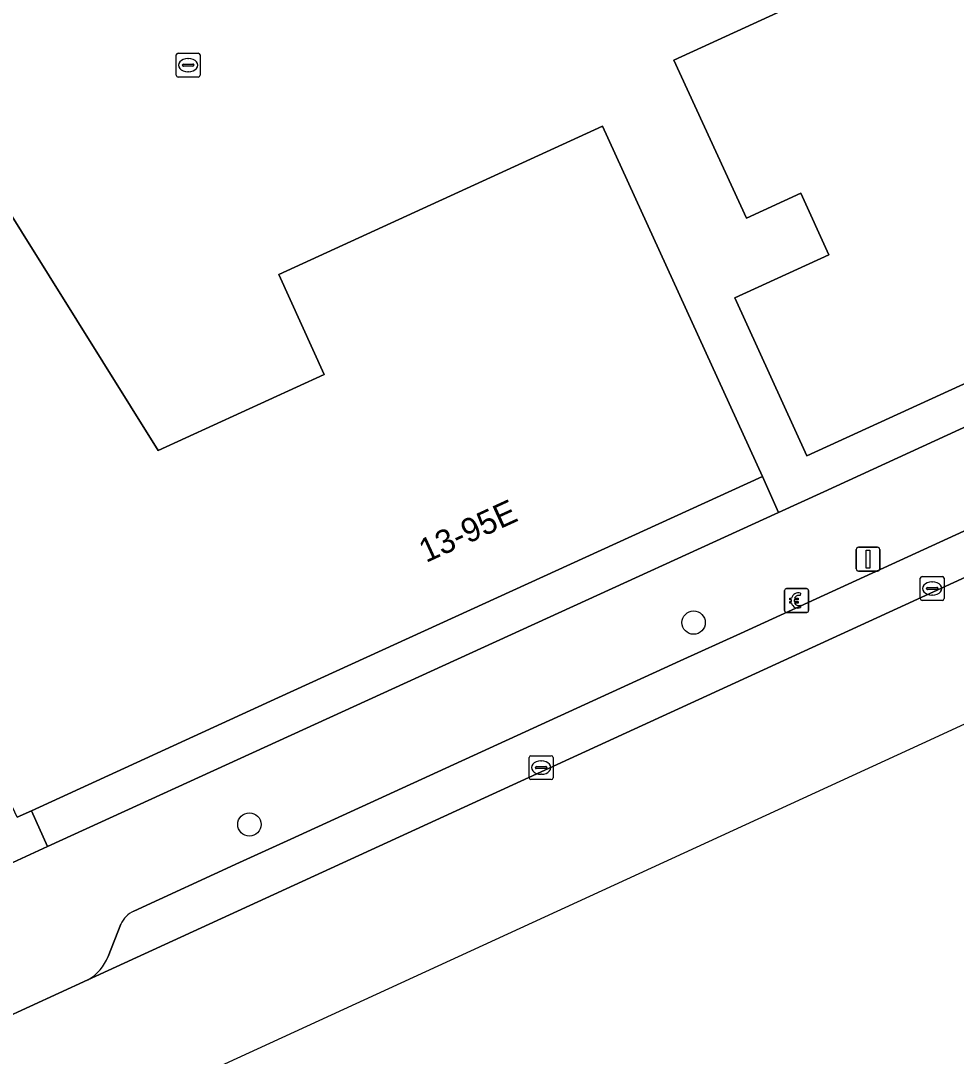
# Model space of a CAD drawing. Extents: x 160377 to 161131, y 383938 to 384853.
# Drawn here: x 161013.88 to 161053.13, y 383997.82 to 384041.25 of the extents above; entities that cross this region are included whole.
import ezdxf

# ---------------------------------------------------------------- set-up
doc = ezdxf.new("R2010")
doc.units = 0
for name, color, linetype in [('IMGEO_Betaalautomaat', 7, 'Continuous'), ('IMGEO_Boom', 7, 'Continuous'), ('IMGEO_Erf', 7, 'Continuous'), ('IMGEO_Kolk', 7, 'Continuous'), ('IMGEO_Lichtmast', 7, 'Continuous'), ('IMGEO_Pand', 7, 'Continuous'), ('IMGEO_Pand_nummerreeks', 7, 'Continuous'), ('IMGEO_Parkeervlak_open', 7, 'Continuous'), ('IMGEO_Rijbaan_lokaal_open', 7, 'Continuous'), ('IMGEO_Voetpad_open', 7, 'Continuous')]:
    doc.layers.add(name, color=color, linetype=linetype)

msp = doc.modelspace()

# ---------------------------------------------------------------- linework, layer by layer
at = {"layer": 'IMGEO_Betaalautomaat'}
for p, q in [((161045.925, 384016.507), (161045.925, 384017.348)), ((161045.925, 384017.348), (161045.925, 384016.507)), ((161046, 384017.431), (161046.841, 384017.431)), ((161046.841, 384017.431), (161046, 384017.431)), ((161046.924, 384017.357), (161046.924, 384016.516)), ((161046.924, 384016.516), (161046.924, 384017.357)), ((161046.208, 384016.895), (161046.208, 384016.963)), ((161046.329, 384016.963), (161046.329, 384016.895)), ((161046.587, 384017.236), (161046.57, 384017.136)), ((161046.85, 384016.432), (161046.009, 384016.432)), ((161046.009, 384016.432), (161046.85, 384016.432)), ((161046.574, 384016.73), (161046.596, 384016.643))]:
    msp.add_line(p, q, dxfattribs=at)
for points in [[(161046.208, 384016.963), (161046.139, 384016.963), (161046.139, 384017.032), (161046.218, 384017.032)], [(161046.213, 384016.826), (161046.139, 384016.826), (161046.139, 384016.895), (161046.208, 384016.895)], [(161046.34, 384017.032), (161046.487, 384017.032), (161046.487, 384016.963), (161046.329, 384016.963)], [(161046.329, 384016.895), (161046.487, 384016.895), (161046.487, 384016.826), (161046.343, 384016.826)]]:
    msp.add_lwpolyline(points, dxfattribs=at)
for centre, radius, start, end in [((161046.003, 384017.354), 0.0779, 92.4484, 184.2845), ((161046.003, 384017.354), 0.0779, 92.4484, 184.2845), ((161046.847, 384017.354), 0.0779, 2.4484, 94.2845), ((161046.847, 384017.354), 0.0779, 2.4484, 94.2845), ((161046.501, 384016.956), 0.293, 73.014, 165.0139), ((161046.507, 384016.969), 0.179, 69.3236, 159.5683), ((161046.003, 384016.51), 0.0779, 182.4484, 274.2845), ((161046.003, 384016.51), 0.0779, 182.4484, 274.2845), ((161046.474, 384016.881), 0.267, 191.8096, 297.0389), ((161046.507, 384016.896), 0.179, 202.7625, 291.8693), ((161046.847, 384016.51), 0.0779, 272.4484, 4.2845), ((161046.847, 384016.51), 0.0779, 272.4484, 4.2845)]:
    msp.add_arc(centre, radius, start, end, dxfattribs=at)
at = {"layer": 'IMGEO_Boom'}
for centre in [(161042.106, 384016.005), (161023.471, 384007.54)]:
    msp.add_circle(centre, 0.489, dxfattribs=at)
at = {"layer": 'IMGEO_Erf'}
for points in [[(161069.225, 384033.241), (161046.86, 384023.007), (161043.831, 384029.622), (161047.785, 384031.433), (161046.605, 384034.011), (161044.32, 384032.962), (161041.279, 384039.589), (161048.269, 384042.808)], [(161009.325, 384039.731), (161019.643, 384023.219), (161026.605, 384026.414), (161024.703, 384030.612), (161038.283, 384036.825), (161044.998, 384022.139), (161045.662, 384020.629), (161047.562, 384021.484), (161073.95, 384033.616), (161074.612, 384033.993)]]:
    msp.add_lwpolyline(points, dxfattribs=at)
at = {"layer": 'IMGEO_Kolk'}
for p, q in [((161020.476, 384039.887), (161021.328, 384039.887)), ((161020.401, 384038.961), (161020.401, 384039.813)), ((161020.703, 384039.43), (161021.101, 384039.43)), ((161020.889, 384039.667), (161020.914, 384039.667)), ((161021.402, 384039.813), (161021.402, 384038.961)), ((161020.66, 384039.381), (161020.66, 384039.393)), ((161021.098, 384039.344), (161020.7, 384039.344)), ((161020.912, 384039.107), (161020.887, 384039.107)), ((161021.144, 384039.393), (161021.144, 384039.381)), ((161021.328, 384038.887), (161020.476, 384038.887)), ((161051.614, 384017.011), (161051.614, 384017.863)), ((161051.689, 384017.937), (161052.541, 384017.937)), ((161052.102, 384017.717), (161052.127, 384017.717)), ((161052.615, 384017.863), (161052.615, 384017.011)), ((161051.873, 384017.431), (161051.873, 384017.443)), ((161052.311, 384017.394), (161051.913, 384017.394)), ((161051.916, 384017.48), (161052.314, 384017.48)), ((161052.357, 384017.443), (161052.357, 384017.431)), ((161052.541, 384016.937), (161051.689, 384016.937)), ((161052.125, 384017.157), (161052.1, 384017.157)), ((161035.208, 384009.497), (161035.208, 384010.349)), ((161035.283, 384010.423), (161036.135, 384010.423)), ((161036.209, 384010.349), (161036.209, 384009.497)), ((161035.467, 384009.917), (161035.467, 384009.929)), ((161035.51, 384009.966), (161035.908, 384009.966)), ((161035.696, 384010.203), (161035.721, 384010.203)), ((161035.951, 384009.929), (161035.951, 384009.917)), ((161035.905, 384009.88), (161035.507, 384009.88)), ((161035.719, 384009.643), (161035.694, 384009.643)), ((161036.135, 384009.423), (161035.283, 384009.423))]:
    msp.add_line(p, q, dxfattribs=at)
for points in [[(161020.476, 384039.887), (161021.328, 384039.887)], [(161020.401, 384038.961), (161020.401, 384039.813)], [(161021.402, 384039.813), (161021.402, 384038.961)], [(161021.328, 384038.887), (161020.476, 384038.887)], [(161051.614, 384017.011), (161051.614, 384017.863)], [(161051.689, 384017.937), (161052.541, 384017.937)], [(161052.615, 384017.863), (161052.615, 384017.011)], [(161052.541, 384016.937), (161051.689, 384016.937)], [(161035.208, 384009.497), (161035.208, 384010.349)], [(161035.283, 384010.423), (161036.135, 384010.423)], [(161036.209, 384010.349), (161036.209, 384009.497)], [(161036.135, 384009.423), (161035.283, 384009.423)]]:
    msp.add_lwpolyline(points, dxfattribs=at)
for centre, radius, start, end in [((161020.478, 384039.811), 0.0765, 91.552, 178.448), ((161020.478, 384039.811), 0.0765, 91.552, 178.448), ((161021.326, 384039.811), 0.0765, 1.552, 88.448), ((161021.326, 384039.811), 0.0765, 1.552, 88.448), ((161020.7, 384039.39), 0.0403, 85.8775, 175.7526), ((161021.105, 384039.392), 0.0386, 1.7309, 96.639), ((161020.697, 384039.38), 0.0366, 178.938, 274.7102), ((161021.101, 384039.387), 0.043, 264.8664, 352.4533), ((161020.478, 384038.963), 0.0765, 181.552, 268.448), ((161020.478, 384038.963), 0.0765, 181.552, 268.448), ((161021.326, 384038.963), 0.0765, 271.552, 358.448), ((161021.326, 384038.963), 0.0765, 271.552, 358.448), ((161051.691, 384017.861), 0.0765, 91.552, 178.448), ((161051.691, 384017.861), 0.0765, 91.552, 178.448), ((161052.539, 384017.861), 0.0765, 1.552, 88.448), ((161052.539, 384017.861), 0.0765, 1.552, 88.448), ((161051.913, 384017.44), 0.0403, 85.8775, 175.7526), ((161051.91, 384017.43), 0.0366, 178.938, 274.7102), ((161052.314, 384017.437), 0.043, 264.8664, 352.4533), ((161052.318, 384017.442), 0.0386, 1.7309, 96.639), ((161051.691, 384017.013), 0.0765, 181.552, 268.448), ((161051.691, 384017.013), 0.0765, 181.552, 268.448), ((161052.539, 384017.013), 0.0765, 271.552, 358.448), ((161052.539, 384017.013), 0.0765, 271.552, 358.448), ((161035.285, 384010.347), 0.0765, 91.552, 178.448), ((161035.285, 384010.347), 0.0765, 91.552, 178.448), ((161036.133, 384010.347), 0.0765, 1.552, 88.448), ((161036.133, 384010.347), 0.0765, 1.552, 88.448), ((161035.507, 384009.926), 0.0403, 85.8775, 175.7526), ((161035.504, 384009.916), 0.0366, 178.938, 274.7102), ((161035.908, 384009.923), 0.043, 264.8664, 352.4533), ((161035.912, 384009.928), 0.0386, 1.7309, 96.639), ((161035.285, 384009.499), 0.0765, 181.552, 268.448), ((161035.285, 384009.499), 0.0765, 181.552, 268.448), ((161036.133, 384009.499), 0.0765, 271.552, 358.448), ((161036.133, 384009.499), 0.0765, 271.552, 358.448)]:
    msp.add_arc(centre, radius, start, end, dxfattribs=at)
for centre, major_axis, ratio, start_param, end_param in [((161020.888, 384039.387), (-0.387, 0.002), 0.722429, 4.712389, 7.853982), ((161020.913, 384039.387), (-0.39, 0.002), 0.717154, 1.570796, 4.712389), ((161052.101, 384017.437), (-0.387, 0.002), 0.722429, 4.712389, 7.853982), ((161052.126, 384017.437), (-0.39, 0.002), 0.717154, 1.570796, 4.712389), ((161035.695, 384009.923), (-0.387, 0.002), 0.722429, 4.712389, 7.853982), ((161035.72, 384009.923), (-0.39, 0.002), 0.717154, 1.570796, 4.712389)]:
    msp.add_ellipse(centre, major_axis=major_axis, ratio=ratio, start_param=start_param, end_param=end_param, dxfattribs=at)
at = {"layer": 'IMGEO_Lichtmast'}
for p, q in [((161048.926, 384018.266), (161048.926, 384019.066)), ((161048.926, 384019.066), (161048.926, 384018.266)), ((161049.026, 384019.166), (161049.816, 384019.166)), ((161049.816, 384019.166), (161049.026, 384019.166)), ((161049.916, 384019.066), (161049.916, 384018.266)), ((161049.916, 384018.266), (161049.916, 384019.066)), ((161049.816, 384018.166), (161049.026, 384018.166)), ((161049.026, 384018.166), (161049.816, 384018.166))]:
    msp.add_line(p, q, dxfattribs=at)
msp.add_lwpolyline([(161049.346, 384019.041), (161049.496, 384019.041), (161049.496, 384018.291), (161049.346, 384018.291), (161049.346, 384019.041)], dxfattribs=at)
for centre, start, end in [((161049.026, 384019.066), 90, 180), ((161049.026, 384019.066), 90, 180), ((161049.816, 384019.066), 0, 90), ((161049.816, 384019.066), 360, 90), ((161049.026, 384018.266), 180, 270), ((161049.026, 384018.266), 180, 270), ((161049.816, 384018.266), 270, 0), ((161049.816, 384018.266), 270, 0)]:
    msp.add_arc(centre, 0.1, start, end, dxfattribs=at)
at = {"layer": 'IMGEO_Pand'}
for points in [[(161048.269, 384042.808), (161041.279, 384039.589), (161044.32, 384032.962), (161046.605, 384034.011), (161047.785, 384031.433), (161043.831, 384029.622), (161046.86, 384023.007), (161069.225, 384033.241)], [(161013.73, 384007.845), (161014.324, 384008.117), (161024.693, 384012.86), (161044.998, 384022.139), (161038.283, 384036.825), (161024.703, 384030.612), (161026.605, 384026.414), (161019.643, 384023.219), (161009.325, 384039.731)]]:
    msp.add_lwpolyline(points, dxfattribs=at)
at = {"layer": 'IMGEO_Parkeervlak_open'}
for points in [[(161074.162, 384029.337), (161044.069, 384015.547), (161041.548, 384014.402), (161025.206, 384006.923), (161023.057, 384005.944), (161018.622, 384003.898)], [(161016.691, 384001.021), (161077.47, 384028.899)], [(161018.081, 384003.352), (161017.544, 384002.003)]]:
    msp.add_lwpolyline(points, dxfattribs=at)
for centre, radius, start, end in [((161018.995, 384002.987), 0.984, 112.279, 158.2481), ((161015.766, 384002.686), 1.905, 299.0539, 338.9886)]:
    msp.add_arc(centre, radius, start, end, dxfattribs=at)
at = {"layer": 'IMGEO_Rijbaan_lokaal_open'}
msp.add_lwpolyline([(160907.425, 383944.713), (161008.487, 383991.097), (161051.698, 384010.93), (161091.48, 384029.287), (161091.391, 384029.491), (161089.312, 384034.241), (161088.837, 384034.033), (161088.05, 384033.688), (161078.568, 384029.392), (161077.47, 384028.899), (161016.691, 384001.021), (161013.046, 383999.338), (161012.775, 383999.215), (160997.494, 383992.318), (160995.778, 383991.468), (160976.307, 383982.559), (160969.412, 383979.39), (160962.893, 383976.427), (160952.387, 383971.601), (160950.34, 383970.771), (160939.561, 383966.391), (160931.592, 383964.679)], dxfattribs=at)
at = {"layer": 'IMGEO_Voetpad_open'}
for points in [[(161002.829, 384017.939), (161003.747, 384018.488), (161000, 384024.459), (160997.809, 384027.95), (160996.896, 384027.38), (160994.826, 384030.694), (160995.573, 384031.201), (160988.066, 384043.19), (160987.32, 384042.691), (160979.403, 384055.414), (160978.717, 384056.538), (160978.313, 384057.179), (160976.857, 384059.536), (160975.962, 384059.006), (161009.9, 384004.269), (161015.004, 384006.614), (161014.324, 384008.117), (161013.73, 384007.845), (161013.438, 384008.48), (161009.85, 384006.769)], [(161024.693, 384012.86), (161014.324, 384008.117), (161015.004, 384006.614), (161045.662, 384020.629), (161044.998, 384022.139)]]:
    msp.add_lwpolyline(points, close=True, dxfattribs=at)
for points in [[(161077.47, 384028.899), (161078.568, 384029.392), (161078.101, 384030.377), (161088.373, 384035.017), (161088.837, 384034.033), (161089.312, 384034.241), (161089.895, 384034.512), (161087.891, 384038.916), (161087.425, 384039.885), (161087.222, 384039.848), (161083.394, 384038.028), (161080.188, 384036.578), (161073.95, 384033.616), (161047.562, 384021.484), (161045.662, 384020.629), (161015.004, 384006.614), (161009.9, 384004.269), (161005.582, 384002.285), (161005.957, 384001.696)], [(161018.622, 384003.898), (161023.057, 384005.944), (161025.206, 384006.923), (161041.548, 384014.402), (161044.069, 384015.547), (161074.162, 384029.337)], [(161017.544, 384002.003), (161018.081, 384003.352)], [(161012.775, 383999.215), (161013.046, 383999.338), (161016.691, 384001.021)]]:
    msp.add_lwpolyline(points, dxfattribs=at)
for centre, radius, start, end in [((161018.995, 384002.987), 0.984, 112.279, 158.2481), ((161015.766, 384002.686), 1.905, 299.0539, 338.9886)]:
    msp.add_arc(centre, radius, start, end, dxfattribs=at)

# ---------------------------------------------------------------- texts
at = {"layer": 'IMGEO_Pand_nummerreeks'}
msp.add_text('13-95E', height=1, rotation=24.6046, dxfattribs=at).set_placement((161030.879, 384018.501))

doc.saveas('drawing.dxf')
